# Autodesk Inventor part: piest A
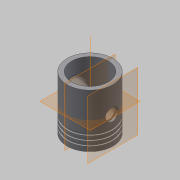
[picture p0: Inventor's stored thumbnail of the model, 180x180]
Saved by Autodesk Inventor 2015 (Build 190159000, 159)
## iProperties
Created: 2009-03
Part Number: piest A
Document SubType Name: Modeling
Designer: Skola
Material: Všeobecné
Density: 1 g/cm^3
Mass: 11.1595 g
Surface Area: 83.1548 cm^2
Volume: 11.1595 cm^3
Appearance: Výchozí
Author: Skola
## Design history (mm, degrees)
sketch "Náčrt1"
  geometry: C1 r 15 at (-12.621, 2.33)
  constraints: 1 centre point
  dimensions: "d0" = 30 diameter of C1
extrude "Vysunutí1" new body sketch "Náčrt1" distance "d1" = 35; taper "d2" = 0 deg
feature "Skořepina1" dims "d3" = 3
node "Pracovní rovina1"
sketch "Náčrt2"
  geometry: L1 (-15, 0)-(15, 0) reference; C1 r 7.5 at (0, 18)
  constraints: 1 centre point
  dimensions: "d4" = 15 diameter of C1; "d22" = 18 distance from line of L1 C1.centre
extrude "Vysunutí2" join sketch "Náčrt2" distance "d5" = 7; taper "d6" = -15 deg
node "Pracovní rovina2"
sketch "Náčrt4"
  geometry: C1 r 15 at (0, 0) reference; C2 r 15 at (0, 0); C3 r 42.591 at (0, 0)
  constraints: 2 centre point, 2 coincident, 1 concentric
extrude "Vysunutí4" cut sketch "Náčrt4" distance "d11" = 50; taper "d12" = 0 deg
node "Pracovní rovina3"
node "Pracovní rovina4"
node "Pracovní rovina5"
mirror "Zrcadlit1"
sketch "Náčrt6"
  geometry: L1 (-15, 0)-(-15, 35) reference; L2 (-15, 0)-(15, 0) reference; 1 further point
  dimensions: "d25" = 15 distance from line of L1 point (0, 18); "d26" = 18 distance from line of L2 point (0, 18)
hole "Díra2" sketch "Náčrt6" at (0, 18) diameter "d27" = 8; stored, may be unused: countersink angle "d31" = 90 deg, drill point angle "d33" = 118 deg; dims "d28" = 6, "d29" = 4, "d30" = 2, "d32" = 8
sketch "Náčrt7"
  geometry: L1 (-15, 0)-(15, 0) reference; L2 (15, 0)-(15, 35) reference; L3 (0, -1.703)-(0, 0); A1 r 73.716 centre (-0.77, 72.01) between (0, -1.703) and (15, 0)
  constraints: 2 end point, 2 point on circle, 1 centre point, 1 midpoint
revolve "Rotace1" sketch "Náčrt7" stored, may be unused: angle "d34" = 90 deg
fillet "Zaoblení2" dims "d35" = 1
chamfer "Zkosení1" distance "d36" = 0.3; stored, may be unused: second distance "d37" = 2, angle "d38" = 45 deg
node "Pracovní rovina6"
sketch "Náčrt8"
  geometry: L1 (-25.121, -2.67)-(-25.921, -2.67); L2 (-25.921, -2.67)-(-25.921, -0.989); L3 (-25.921, -0.989)-(-25.121, -0.989); L4 (-25.121, -0.989)-(-25.121, -2.67); L5 (-26.778, -1.67)-(-17.621, -1.67) reference; L6 (-15.485, 2.33)-(-34.883, 2.33); L7 (-17.621, 7.954)-(-17.621, -3.294) reference
  constraints: 10 end point, 3 parallel, 1 horizontal, 1 perpendicular
  dimensions: "d40" = 8 diameter of L5 L6; "d41" = 7.5 distance between parallel lines of L4 L7; "d42" = 0.8 distance of L2.end L3.end; "d43" = 1 distance between parallel lines of L1 L5
revolve "Rotace2" sketch "Náčrt8" stored, may be unused: angle "d44" = 90 deg
mirror "Zrcadlit2"
node "Pracovní osa1"
sketch "Náčrt9"
  geometry: L1 (-15, 0)-(-15, 35) reference; L2 (-15, 3)-(-14, 3); L3 (-14, 3)-(-14, 4.5); L4 (-14, 4.5)-(-15, 4.5); L5 (-15, 4.5)-(-15, 3); L6 (-15, 6)-(-14, 6); L7 (-14, 6)-(-14, 7.5); L8 (-14, 7.5)-(-15, 7.5); L9 (-15, 7.5)-(-15, 6); L10 (-15, 9)-(-14, 9); L11 (-14, 9)-(-14, 10.5); L12 (-14, 10.5)-(-15, 10.5); L13 (-15, 10.5)-(-15, 9); L14 (0, -9.043)-(0, 42.341) reference; 1 further point
  constraints: 24 end point, 6 parallel, 3 horizontal, 3 perpendicular, 3 point on line
  dimensions: "d45" = 1.5 distance of L2.end L3.end; "d46" = 1 distance of L2.start L2.end; "d47" = 3 distance from line of L2 L1.start; "d48" = 1.5 distance of L6.end L7.end; "d49" = 1.5 distance of L10.end L11.end; "d50" = 1.5 distance between parallel lines of L6 L4; "d51" = 1.5 distance between parallel lines of L10 L8
revolve "Rotace3" sketch "Náčrt9" stored, may be unused: angle "d52" = 90 deg
node "Těleso1"
node "Objemová tělesa"
node "Povrchová tělesa"
other parameters: "d7" = 42, "d24" = -15, "d39" = 18
